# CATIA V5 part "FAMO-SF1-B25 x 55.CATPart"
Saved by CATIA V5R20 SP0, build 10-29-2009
Part number: FAMO-SF1-B25 x 55
Definition: NONE
Nomenclature: FAMO-SF1-B25 x 55
Source: Unknown
Description: FAMO-SF1-B25 x 55
Bounding box of the stored display mesh (mm): x -13 to 42, y -22 to 22, z -22 to 22
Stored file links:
  C:\Users\Utente\Desktop\IO LAVORO\3D X SITO CF\X SITO\FAMO\FAMO-SF1-B25 x 55.CATPart
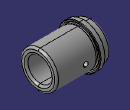
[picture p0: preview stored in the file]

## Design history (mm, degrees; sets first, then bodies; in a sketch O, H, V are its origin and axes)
Body1 "FAMO-SF1-B25 x 55" (main body)
  Solid1: solid without history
